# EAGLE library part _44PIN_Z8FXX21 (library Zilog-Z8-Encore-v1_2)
Z8 Encore, LQFP-44 /PLCC-44 Packages
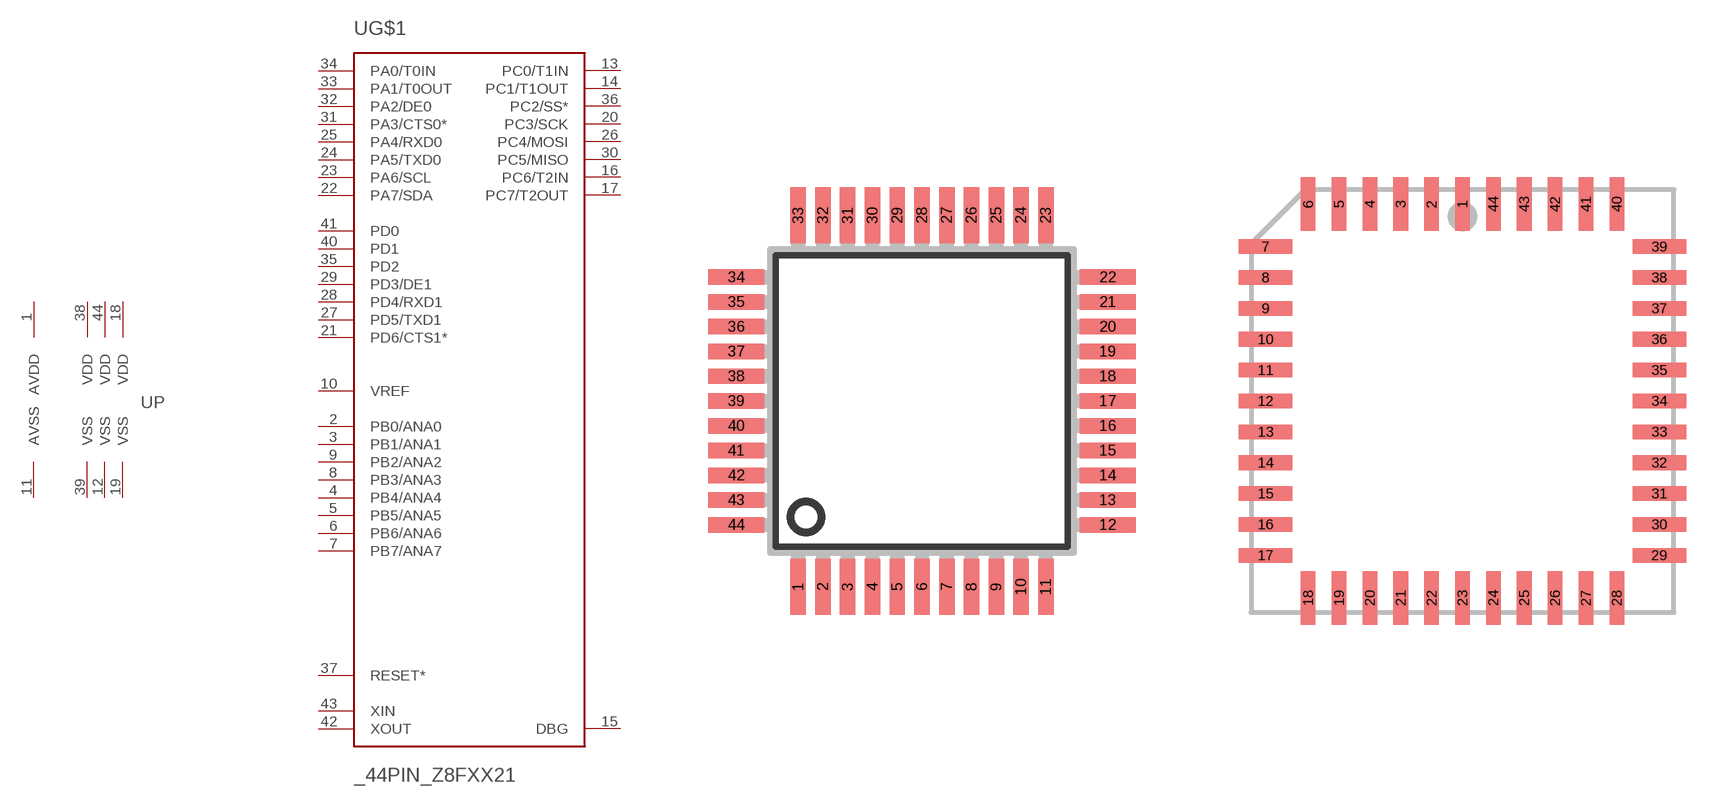
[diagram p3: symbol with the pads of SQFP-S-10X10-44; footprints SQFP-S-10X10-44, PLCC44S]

Designator prefix U; gates G$1=Z8FXX21 P=PWR_44-PIN

## _44PIN_Z8FXX21AN  [SQFP-S-10X10-44]
1  P:AVDD  pwr
2  G$1:PB0/ANA0
3  G$1:PB1/ANA1
4  G$1:PB4/ANA4
5  G$1:PB5/ANA5
6  G$1:PB6/ANA6
7  G$1:PB7/ANA7
8  G$1:PB3/ANA3
9  G$1:PB2/ANA2
10  G$1:VREF  pas
11  P:AVSS  pwr
12  P:VSS  pwr
13  G$1:PC0/T1IN
14  G$1:PC1/T1OUT
15  G$1:DBG
16  G$1:PC6/T2IN
17  G$1:PC7/T2OUT
18  P:VDD  pwr
19  P:VSS  pwr
20  G$1:PC3/SCK
21  G$1:PD6/CTS1*
22  G$1:PA7/SDA
23  G$1:PA6/SCL
24  G$1:PA5/TXD0
25  G$1:PA4/RXD0
26  G$1:PC4/MOSI
27  G$1:PD5/TXD1
28  G$1:PD4/RXD1
29  G$1:PD3/DE1
30  G$1:PC5/MISO
31  G$1:PA3/CTS0*
32  G$1:PA2/DE0
33  G$1:PA1/T0OUT
34  G$1:PA0/T0IN
35  G$1:PD2
36  G$1:PC2/SS*
37  G$1:RESET*  in
38  P:VDD  pwr
39  P:VSS  pwr
40  G$1:PD1
41  G$1:PD0
42  G$1:XOUT  out
43  G$1:XIN  in
44  P:VDD  pwr

## _44PIN_Z8FXX21VN  [PLCC44S]
1  G$1:PD4/RXD1
2  G$1:PD3/DE1
3  G$1:PC5/MISO
4  G$1:PA3/CTS0*
5  G$1:PA2/DE0
6  G$1:PA1/T0OUT
7  G$1:PA0/T0IN
8  G$1:PD2
9  G$1:PC2/SS*
10  G$1:RESET*  in
11  P:VDD  pwr
12  P:VSS  pwr
13  G$1:PD1
14  G$1:PD0
15  G$1:XOUT  out
16  G$1:XIN  in
17  P:VDD  pwr
18  P:AVDD  pwr
19  G$1:PB0/ANA0
20  G$1:PB1/ANA1
21  G$1:PB4/ANA4
22  G$1:PB5/ANA5
23  G$1:PB6/ANA6
24  G$1:PB7/ANA7
25  G$1:PB3/ANA3
26  G$1:PB2/ANA2
27  G$1:VREF  pas
28  P:AVSS  pwr
29  P:VSS  pwr
30  G$1:PC0/T1IN
31  G$1:PC1/T1OUT
32  G$1:DBG
33  G$1:PC6/T2IN
34  G$1:PC7/T2OUT
35  P:VDD  pwr
36  P:VSS  pwr
37  G$1:PC3/SCK
38  G$1:PD6/CTS1*
39  G$1:PA7/SDA
40  G$1:PA6/SCL
41  G$1:PA5/TXD0
42  G$1:PA4/RXD0
43  G$1:PC4/MOSI
44  G$1:PD5/TXD1

## _44PIN_Z8FXX21VN-SMS  [PLCCSM44]
Pads as for PLCC44S

## _44PIN_Z8FXX21VN-THS  [PLCC-S44]
Pads as for PLCC44S

## Footprint SQFP-S-10X10-44 (pad centres in mm)
LQFP-44 shrink quad flat pack, square
smd 0.5 x 1.8: 1 -4,-6; 2 -3.2,-6; 3 -2.4,-6; 4 -1.6,-6; 5 -0.8,-6; 6 0,-6; 7 0.8,-6; 8 1.6,-6; 9 2.4,-6; 10 3.2,-6; 11 4,-6; 23 4,6; 24 3.2,6; 25 2.4,6; 26 1.6,6; 27 0.8,6; 28 0,6; 29 -0.8,6; 30 -1.6,6; 31 -2.4,6; 32 -3.2,6; 33 -4,6
smd 1.8 x 0.5: 12 6,-4; 13 6,-3.2; 14 6,-2.4; 15 6,-1.6; 16 6,-0.8; 17 6,0; 18 6,0.8; 19 6,1.6; 20 6,2.4; 21 6,3.2; 22 6,4; 34 -6,4; 35 -6,3.2; 36 -6,2.4; 37 -6,1.6; 38 -6,0.8; 39 -6,0; 40 -6,-0.8; 41 -6,-1.6; 42 -6,-2.4; 43 -6,-3.2; 44 -6,-4

## Footprint PLCC44S (pad centres in mm)
PLCC-44
smd 0.6 x 2.2: 1 0,8.1; 2 -1.27,8.1; 3 -2.54,8.1; 4 -3.81,8.1; 5 -5.08,8.1; 6 -6.35,8.1; 18 -6.35,-8.1; 19 -5.08,-8.1; 20 -3.81,-8.1; 21 -2.54,-8.1; 22 -1.27,-8.1; 23 0,-8.1; 24 1.27,-8.1; 25 2.54,-8.1; 26 3.81,-8.1; 27 5.08,-8.1; 28 6.35,-8.1; 40 6.35,8.1; 41 5.08,8.1; 42 3.81,8.1; 43 2.54,8.1; 44 1.27,8.1
smd 2.2 x 0.6: 7 -8.1,6.35; 8 -8.1,5.08; 9 -8.1,3.81; 10 -8.1,2.54; 11 -8.1,1.27; 12 -8.1,0; 13 -8.1,-1.27; 14 -8.1,-2.54; 15 -8.1,-3.81; 16 -8.1,-5.08; 17 -8.1,-6.35; 29 8.1,-6.35; 30 8.1,-5.08; 31 8.1,-3.81; 32 8.1,-2.54; 33 8.1,-1.27; 34 8.1,0; 35 8.1,1.27; 36 8.1,2.54; 37 8.1,3.81; 38 8.1,5.08; 39 8.1,6.35

## Footprint PLCCSM44 (pad centres in mm)
PLCC-44 Surface-Mount Socket
smd 0.66 x 2.591: 1 0,8.89; 2 -1.27,8.89; 3 -2.54,8.89; 4 -3.81,8.89; 5 -5.08,8.89; 6 -6.35,8.89; 18 -6.35,-8.89; 19 -5.08,-8.89; 20 -3.81,-8.89; 21 -2.54,-8.89; 22 -1.27,-8.89; 23 0,-8.89; 24 1.27,-8.89; 25 2.54,-8.89; 26 3.81,-8.89; 27 5.08,-8.89; 28 6.35,-8.89; 40 6.35,8.89; 41 5.08,8.89; 42 3.81,8.89; 43 2.54,8.89; 44 1.27,8.89
smd 2.591 x 0.66: 7 -8.89,6.35; 8 -8.89,5.08; 9 -8.89,3.81; 10 -8.89,2.54; 11 -8.89,1.27; 12 -8.89,0; 13 -8.89,-1.27; 14 -8.89,-2.54; 15 -8.89,-3.81; 16 -8.89,-5.08; 17 -8.89,-6.35; 29 8.89,-6.35; 30 8.89,-5.08; 31 8.89,-3.81; 32 8.89,-2.54; 33 8.89,-1.27; 34 9.017,0; 35 8.89,1.27; 36 8.89,2.54; 37 8.89,3.81; 38 8.89,5.08; 39 8.89,6.35

## Footprint PLCC-S44 (pad centres in mm)
PLCC-44 Thru-Hole Socket
drill 0.813 round: 1 1.27,6.35
drill 0.813 octagon: 2 -1.27,8.89; 3 -1.27,6.35; 4 -3.81,8.89; 5 -3.81,6.35; 6 -6.35,8.89; 7 -8.89,6.35; 8 -6.35,6.35; 9 -8.89,3.81; 10 -6.35,3.81; 11 -8.89,1.27; 12 -6.35,1.27; 13 -8.89,-1.27; 14 -6.35,-1.27; 15 -8.89,-3.81; 16 -6.35,-3.81; 17 -8.89,-6.35; 18 -6.35,-8.89; 19 -6.35,-6.35; 20 -3.81,-8.89; 21 -3.81,-6.35; 22 -1.27,-8.89; 23 -1.27,-6.35; 24 1.27,-8.89; 25 1.27,-6.35; 26 3.81,-8.89; 27 3.81,-6.35; 28 6.35,-8.89; 29 8.89,-6.35; 30 6.35,-6.35; 31 8.89,-3.81; 32 6.35,-3.81; 33 8.89,-1.27; 34 6.35,-1.27; 35 8.89,1.27; 36 6.35,1.27; 37 8.89,3.81; 38 6.35,3.81; 39 8.89,6.35; 40 6.35,8.89; 41 6.35,6.35; 42 3.81,8.89; 43 3.81,6.35; 44 1.27,8.89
